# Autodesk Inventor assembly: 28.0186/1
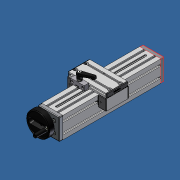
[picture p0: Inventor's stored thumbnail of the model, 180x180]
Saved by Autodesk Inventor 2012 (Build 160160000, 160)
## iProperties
Created: 2007-06
Part Number: 28.0186/1
Document SubType Name: Assembly
Designer: Andy Moles
Description: ADJUSTING UNIT VEN 90 WITH TOP CLAMP
Author: Andy Moles
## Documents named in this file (20)
- C:\Andys Backup Data\ANDY'S INVENTOR\INVENTOR LIBRARIES\PARTS LIBRARY\READY FOR USE MODULES LG\28.0186_1 ADJUSTING UNIT VEN 90 WITH TOP CLAMP.iam
- C:\Andys Backup Data\ANDY'S INVENTOR\INVENTOR LIBRARIES\PARTS LIBRARY\READY FOR USE MODULES LG\SUBCOMPONENTS\50.1264 BALL BEARING 10X30X9 6200 2RS DIN 625.ipt
- C:\Andys Backup Data\ANDY'S INVENTOR\INVENTOR LIBRARIES\PARTS LIBRARY\READY FOR USE MODULES LG\SUBCOMPONENTS\28.0205 BEARING PLATE 90X90 HANDWHEEL SIDE.ipt
- C:\Andys Backup Data\ANDY'S INVENTOR\INVENTOR LIBRARIES\PARTS LIBRARY\READY FOR USE MODULES LG\SUBCOMPONENTS\28.0206 BEARING PLATE 90X90 IDLER SIDE.ipt
- C:\Andys Backup Data\ANDY'S INVENTOR\INVENTOR LIBRARIES\PARTS LIBRARY\READY FOR USE MODULES LG\SUBCOMPONENTS\28.0204 HANDWHEEL 100mm.iam
- C:\Andys Backup Data\ANDY'S INVENTOR\INVENTOR LIBRARIES\PARTS LIBRARY\FASTENING ELEMENTS\NUTS\21.1351 M8 SQUARE NUT.ipt
- C:\Andys Backup Data\ANDY'S INVENTOR\INVENTOR LIBRARIES\PARTS LIBRARY\READY FOR USE MODULES LG\SUBCOMPONENTS\28.0216_3 90x90S TOP LOCK.ipt
- C:\Andys Backup Data\ANDY'S INVENTOR\INVENTOR LIBRARIES\PARTS LIBRARY\FASTENING ELEMENTS\WASHERS\21.1326 DISC SPRING 20.ipt
- C:\Andys Backup Data\ANDY'S INVENTOR\INVENTOR LIBRARIES\PARTS LIBRARY\READY FOR USE MODULES LG\SUBCOMPONENTS\28.0221_1 ACME SCREW 16X4 TOP LOCK.ipt
- C:\Andys Backup Data\ANDY'S INVENTOR\INVENTOR LIBRARIES\PARTS LIBRARY\FASTENING ELEMENTS\SCREWS CAP\21.1204 M8X25.ipt
- C:\Andys Backup Data\ANDY'S INVENTOR\INVENTOR LIBRARIES\PARTS LIBRARY\READY FOR USE MODULES LG\SUBCOMPONENTS\28.0224_1 LWN 32X45-90 90X19-NSC.ipt
- C:\Andys Backup Data\ANDY'S INVENTOR\INVENTOR LIBRARIES\PARTS LIBRARY\READY FOR USE MODULES LG\SUBCOMPONENTS\28.0126 SLIDE 45X32.ipt
- C:\Andys Backup Data\ANDY'S INVENTOR\INVENTOR LIBRARIES\PARTS LIBRARY\READY FOR USE MODULES LG\SUBCOMPONENTS\28.0255 Nut slide connector 20.ipt
- C:\Andys Backup Data\ANDY'S INVENTOR\INVENTOR LIBRARIES\PARTS LIBRARY\READY FOR USE MODULES LG\SUBCOMPONENTS\28.0257 BRONZE NUT 16X4 NOTCHED.ipt
- C:\Andys Backup Data\ANDY'S INVENTOR\INVENTOR LIBRARIES\PARTS LIBRARY\FASTENING ELEMENTS\SCREWS CAP\21.1200 M8X16.ipt
- C:\Andys Backup Data\ANDY'S INVENTOR\INVENTOR LIBRARIES\PARTS LIBRARY\FASTENING ELEMENTS\SCREWS CAP\21.1235 M5X16.ipt
- C:\Andys Backup Data\ANDY'S INVENTOR\INVENTOR LIBRARIES\PARTS LIBRARY\COMPONENTS LR\28.0270_9 SLIDE CLAMPING UNIT 5mm OFFSET..iam
- C:\Andys Backup Data\ANDY'S INVENTOR\INVENTOR LIBRARIES\PARTS LIBRARY\END CAPS\22.1003_1 END CAP 45x32 Z Gray.iam
- C:\Andys Backup Data\ANDY'S INVENTOR\INVENTOR LIBRARIES\PARTS LIBRARY\END CAPS\22.1014_1 END CAP 90X19 GRAY.ipt
- C:\Andys Backup Data\ANDY'S INVENTOR\INVENTOR LIBRARIES\PARTS LIBRARY\COMPONENTS LG\22.1095 SLIDE RAIL LN.iam
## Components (41 placed, 19 different names)
1. 28.0216_3 90x90S TOP LOCK:1 — Flush:9, Mate:9, Mate:10, Mate:11, Flush:10, Flush:11, Flush:12, Mate:13, Flush:13, Flush:14, Mate:33, Mate:34
2. 50.1264 10X30X9 6200 2RS DIN 625 BALL BEARING:1 — Insert:7
3. 50.1264 10X30X9 6200 2RS DIN 625 BALL BEARING:2 — Insert:6, Insert:10
4. 28.0205 BEARING PLATE 90X90 HANDWHEEL SIDE:1 — Insert:4, Insert:7, Mate:11, Flush:10, Flush:11, Insert:11, Insert:12, Insert:13, Insert:14
5. 28.0206 BEARING PLATE 90X90 IDLER SIDE:1 — Insert:6, Flush:12, Mate:13, Flush:13, Flush:14, Insert:15, Insert:16, Insert:17, Insert:18
6. 28.0204 HANDWHEEL 100mm:1 [sub-assembly] — Insert:4
7. 21.1326 DISC SPRING 20:1 — Insert:8
8. 21.1326 DISC SPRING 20:2 — Insert:9, Insert:10
9. 28.0221_1 ACME SCREW 16X4 TOP LOCK:1 — Insert:8, Insert:9, Mate:28
10. 21.1204  M8 x 25:1 — Insert:11
11. 21.1204  M8 x 25:2 — Insert:12
12. 21.1204  M8 x 25:3 — Insert:13
13. 21.1204  M8 x 25:4 — Insert:18
14. 21.1204  M8 x 25:5 — Insert:17
15. 21.1204  M8 x 25:6 — Insert:14
16. 21.1204  M8 x 25:7 — Insert:16
17. 21.1204  M8 x 25:8 — Insert:15
18. 28.0224_1 LWN 32X45-90 90X19-NSC:1 — Insert:19, Insert:20, Insert:21, Insert:22, Insert:23, Insert:24, Insert:25, Angle:5, Insert:26, Insert:27, Insert:28, Insert:29, Angle:6, Angle:7, Angle:8, Angle:9, Mate:17, Flush:15, Flush:16, Mate:18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
19. 28.0126 SLIDE 45X32:1 — Mate:17, Flush:15, Flush:16, Insert:30, Angle:11, Mate:24, Flush:23, Flush:24, Mate:29, Mate:30
20. 28.0126 SLIDE 45X32:2 — Mate:18, Flush:17, Flush:18, Mate:22, Flush:19, Flush:20, Mate:23, Flush:21, Flush:22, Mate:31, Mate:35
21. 28.0255 Nut slide connector 20:1 — Insert:25, Angle:5, Mate:27, Angle:12
22. 28.0257 BRONZE NUT 16X4 NOTCHED:1 — Mate:27, Angle:12, Mate:28
23. 21.1200 M8 x 16:1 — Insert:20
24. 21.1200 M8 x 16:2 — Insert:19
25. 21.1200 M8 x 16:3 — Insert:21
26. 21.1200 M8 x 16:4 — Insert:22
27. 21.1235  M5 x 16:1 — Insert:24
28. 21.1235  M5 x 16:2 — Insert:23
29. 21.1351 M8 SQUARE NUT:2 — Insert:26, Angle:8
30. 21.1351 M8 SQUARE NUT:3 — Insert:27, Angle:9
31. 21.1351 M8 SQUARE NUT:4 — Insert:28, Angle:7
32. 21.1351 M8 SQUARE NUT:5 — Insert:29, Angle:6
33. 28.0270_9 SLIDE CLAMPING UNIT 5mm OFFSET.:1 [sub-assembly] — Mate:19, Angle:10, Mate:20, Mate:21
34. 22.1003\1 END CAP 45x32 Z Gray:1 [sub-assembly] — Insert:30, Angle:11
35. 22.1003\1 END CAP 45x32 Z Gray:2 [sub-assembly] — Mate:22, Flush:19, Flush:20
36. 22.1003\1 END CAP 45x32 Z Gray:3 [sub-assembly] — Mate:24, Flush:23, Flush:24
37. 22.1003\1 END CAP 45x32 Z Gray:4 [sub-assembly] — Mate:23, Flush:21, Flush:22
38. 22.1014_1 END CAP 90X19 GRAY:1 — Mate:25, Flush:25, Flush:26
39. 22.1014_1 END CAP 90X19 GRAY:2 — Mate:26, Flush:27, Flush:28
40. 22.1095 SLIDE RAIL LN:1 [sub-assembly] — Mate:29, Mate:30, Flush:29
41. 22.1095 SLIDE RAIL LN:2 [sub-assembly] — Mate:31, Flush:30, Mate:33, Mate:34, Mate:35
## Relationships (78: Insert 26, Flush 22, Mate 22, Angle 8)
- Insert:4: 28.0205 BEARING PLATE 90X90 HANDWHEEL SIDE:1 ↔ 28.0204 HANDWHEEL 100mm:1
- Flush:9: 28.0216_3 90x90S TOP LOCK:1
- Mate:9: 28.0216_3 90x90S TOP LOCK:1
- Insert:6: 50.1264 10X30X9 6200 2RS DIN 625 BALL BEARING:2 ↔ 28.0206 BEARING PLATE 90X90 IDLER SIDE:1
- Insert:7: 50.1264 10X30X9 6200 2RS DIN 625 BALL BEARING:1 ↔ 28.0205 BEARING PLATE 90X90 HANDWHEEL SIDE:1
- Mate:10: 28.0216_3 90x90S TOP LOCK:1
- Mate:11: 28.0216_3 90x90S TOP LOCK:1 ↔ 28.0205 BEARING PLATE 90X90 HANDWHEEL SIDE:1
- Flush:10: 28.0216_3 90x90S TOP LOCK:1 ↔ 28.0205 BEARING PLATE 90X90 HANDWHEEL SIDE:1
- Flush:11: 28.0216_3 90x90S TOP LOCK:1 ↔ 28.0205 BEARING PLATE 90X90 HANDWHEEL SIDE:1
- Flush:12: 28.0216_3 90x90S TOP LOCK:1 ↔ 28.0206 BEARING PLATE 90X90 IDLER SIDE:1
- Mate:13: 28.0216_3 90x90S TOP LOCK:1 ↔ 28.0206 BEARING PLATE 90X90 IDLER SIDE:1
- Flush:13: 28.0216_3 90x90S TOP LOCK:1 ↔ 28.0206 BEARING PLATE 90X90 IDLER SIDE:1
- Flush:14: 28.0216_3 90x90S TOP LOCK:1 ↔ 28.0206 BEARING PLATE 90X90 IDLER SIDE:1
- Insert:8: 21.1326 DISC SPRING 20:1 ↔ 28.0221_1 ACME SCREW 16X4 TOP LOCK:1
- Insert:9: 21.1326 DISC SPRING 20:2 ↔ 28.0221_1 ACME SCREW 16X4 TOP LOCK:1
- Insert:10: 50.1264 10X30X9 6200 2RS DIN 625 BALL BEARING:2 ↔ 21.1326 DISC SPRING 20:2
- Insert:11: 28.0205 BEARING PLATE 90X90 HANDWHEEL SIDE:1 ↔ 21.1204  M8 x 25:1
- Insert:12: 28.0205 BEARING PLATE 90X90 HANDWHEEL SIDE:1 ↔ 21.1204  M8 x 25:2
- Insert:13: 28.0205 BEARING PLATE 90X90 HANDWHEEL SIDE:1 ↔ 21.1204  M8 x 25:3
- Insert:14: 28.0205 BEARING PLATE 90X90 HANDWHEEL SIDE:1 ↔ 21.1204  M8 x 25:6
- Insert:15: 28.0206 BEARING PLATE 90X90 IDLER SIDE:1 ↔ 21.1204  M8 x 25:8
- Insert:16: 28.0206 BEARING PLATE 90X90 IDLER SIDE:1 ↔ 21.1204  M8 x 25:7
- Insert:17: 28.0206 BEARING PLATE 90X90 IDLER SIDE:1 ↔ 21.1204  M8 x 25:5
- Insert:18: 28.0206 BEARING PLATE 90X90 IDLER SIDE:1 ↔ 21.1204  M8 x 25:4
- Insert:19: 28.0224_1 LWN 32X45-90 90X19-NSC:1 ↔ 21.1200 M8 x 16:2
- Insert:20: 28.0224_1 LWN 32X45-90 90X19-NSC:1 ↔ 21.1200 M8 x 16:1
- Insert:21: 28.0224_1 LWN 32X45-90 90X19-NSC:1 ↔ 21.1200 M8 x 16:3
- Insert:22: 28.0224_1 LWN 32X45-90 90X19-NSC:1 ↔ 21.1200 M8 x 16:4
- Insert:23: 28.0224_1 LWN 32X45-90 90X19-NSC:1 ↔ 21.1235  M5 x 16:2
- Insert:24: 28.0224_1 LWN 32X45-90 90X19-NSC:1 ↔ 21.1235  M5 x 16:1
- Insert:25: 28.0224_1 LWN 32X45-90 90X19-NSC:1 ↔ 28.0255 Nut slide connector 20:1
- Angle:5: 28.0224_1 LWN 32X45-90 90X19-NSC:1 ↔ 28.0255 Nut slide connector 20:1
- Insert:26: 28.0224_1 LWN 32X45-90 90X19-NSC:1 ↔ 21.1351 M8 SQUARE NUT:2
- Insert:27: 28.0224_1 LWN 32X45-90 90X19-NSC:1 ↔ 21.1351 M8 SQUARE NUT:3
- Insert:28: 28.0224_1 LWN 32X45-90 90X19-NSC:1 ↔ 21.1351 M8 SQUARE NUT:4
- Insert:29: 28.0224_1 LWN 32X45-90 90X19-NSC:1 ↔ 21.1351 M8 SQUARE NUT:5
- Angle:6: 28.0224_1 LWN 32X45-90 90X19-NSC:1 ↔ 21.1351 M8 SQUARE NUT:5
- Angle:7: 28.0224_1 LWN 32X45-90 90X19-NSC:1 ↔ 21.1351 M8 SQUARE NUT:4
- Angle:8: 28.0224_1 LWN 32X45-90 90X19-NSC:1 ↔ 21.1351 M8 SQUARE NUT:2
- Angle:9: 28.0224_1 LWN 32X45-90 90X19-NSC:1 ↔ 21.1351 M8 SQUARE NUT:3
- Mate:17: 28.0224_1 LWN 32X45-90 90X19-NSC:1 ↔ 28.0126 SLIDE 45X32:1
- Flush:15: 28.0224_1 LWN 32X45-90 90X19-NSC:1 ↔ 28.0126 SLIDE 45X32:1
- Flush:16: 28.0224_1 LWN 32X45-90 90X19-NSC:1 ↔ 28.0126 SLIDE 45X32:1
- Mate:18: 28.0224_1 LWN 32X45-90 90X19-NSC:1 ↔ 28.0126 SLIDE 45X32:2
- Flush:17: 28.0224_1 LWN 32X45-90 90X19-NSC:1 ↔ 28.0126 SLIDE 45X32:2
- Flush:18: 28.0224_1 LWN 32X45-90 90X19-NSC:1 ↔ 28.0126 SLIDE 45X32:2
- Mate:19: 28.0224_1 LWN 32X45-90 90X19-NSC:1 ↔ 28.0270_9 SLIDE CLAMPING UNIT 5mm OFFSET.:1
- Angle:10: 28.0224_1 LWN 32X45-90 90X19-NSC:1 ↔ 28.0270_9 SLIDE CLAMPING UNIT 5mm OFFSET.:1
- Mate:20: 28.0224_1 LWN 32X45-90 90X19-NSC:1 ↔ 28.0270_9 SLIDE CLAMPING UNIT 5mm OFFSET.:1
- Mate:21: 28.0224_1 LWN 32X45-90 90X19-NSC:1 ↔ 28.0270_9 SLIDE CLAMPING UNIT 5mm OFFSET.:1
- Insert:30: 28.0126 SLIDE 45X32:1 ↔ 22.1003\1 END CAP 45x32 Z Gray:1
- Angle:11: 28.0126 SLIDE 45X32:1 ↔ 22.1003\1 END CAP 45x32 Z Gray:1
- Mate:22: 28.0126 SLIDE 45X32:2 ↔ 22.1003\1 END CAP 45x32 Z Gray:2
- Flush:19: 28.0126 SLIDE 45X32:2 ↔ 22.1003\1 END CAP 45x32 Z Gray:2
- Flush:20: 28.0126 SLIDE 45X32:2 ↔ 22.1003\1 END CAP 45x32 Z Gray:2
- Mate:23: 28.0126 SLIDE 45X32:2 ↔ 22.1003\1 END CAP 45x32 Z Gray:4
- Flush:21: 28.0126 SLIDE 45X32:2 ↔ 22.1003\1 END CAP 45x32 Z Gray:4
- Flush:22: 28.0126 SLIDE 45X32:2 ↔ 22.1003\1 END CAP 45x32 Z Gray:4
- Mate:24: 28.0126 SLIDE 45X32:1 ↔ 22.1003\1 END CAP 45x32 Z Gray:3
- Flush:23: 28.0126 SLIDE 45X32:1 ↔ 22.1003\1 END CAP 45x32 Z Gray:3
- Flush:24: 28.0126 SLIDE 45X32:1 ↔ 22.1003\1 END CAP 45x32 Z Gray:3
- Mate:25: 28.0224_1 LWN 32X45-90 90X19-NSC:1 ↔ 22.1014_1 END CAP 90X19 GRAY:1
- Flush:25: 28.0224_1 LWN 32X45-90 90X19-NSC:1 ↔ 22.1014_1 END CAP 90X19 GRAY:1
- Flush:26: 28.0224_1 LWN 32X45-90 90X19-NSC:1 ↔ 22.1014_1 END CAP 90X19 GRAY:1
- Mate:26: 28.0224_1 LWN 32X45-90 90X19-NSC:1 ↔ 22.1014_1 END CAP 90X19 GRAY:2
- Flush:27: 28.0224_1 LWN 32X45-90 90X19-NSC:1 ↔ 22.1014_1 END CAP 90X19 GRAY:2
- Flush:28: 28.0224_1 LWN 32X45-90 90X19-NSC:1 ↔ 22.1014_1 END CAP 90X19 GRAY:2
- Mate:27: 28.0255 Nut slide connector 20:1 ↔ 28.0257 BRONZE NUT 16X4 NOTCHED:1
- Angle:12: 28.0255 Nut slide connector 20:1 ↔ 28.0257 BRONZE NUT 16X4 NOTCHED:1
- Mate:28: 28.0221_1 ACME SCREW 16X4 TOP LOCK:1 ↔ 28.0257 BRONZE NUT 16X4 NOTCHED:1
- Mate:29: 28.0126 SLIDE 45X32:1 ↔ 22.1095 SLIDE RAIL LN:1
- Mate:30: 28.0126 SLIDE 45X32:1 ↔ 22.1095 SLIDE RAIL LN:1
- Flush:29: 28.0224_1 LWN 32X45-90 90X19-NSC:1 ↔ 22.1095 SLIDE RAIL LN:1
- Mate:31: 28.0126 SLIDE 45X32:2 ↔ 22.1095 SLIDE RAIL LN:2
- Flush:30: 28.0224_1 LWN 32X45-90 90X19-NSC:1 ↔ 22.1095 SLIDE RAIL LN:2
- Mate:33: 28.0216_3 90x90S TOP LOCK:1 ↔ 22.1095 SLIDE RAIL LN:2
- Mate:34: 28.0216_3 90x90S TOP LOCK:1 ↔ 22.1095 SLIDE RAIL LN:2
- Mate:35: 28.0126 SLIDE 45X32:2 ↔ 22.1095 SLIDE RAIL LN:2
